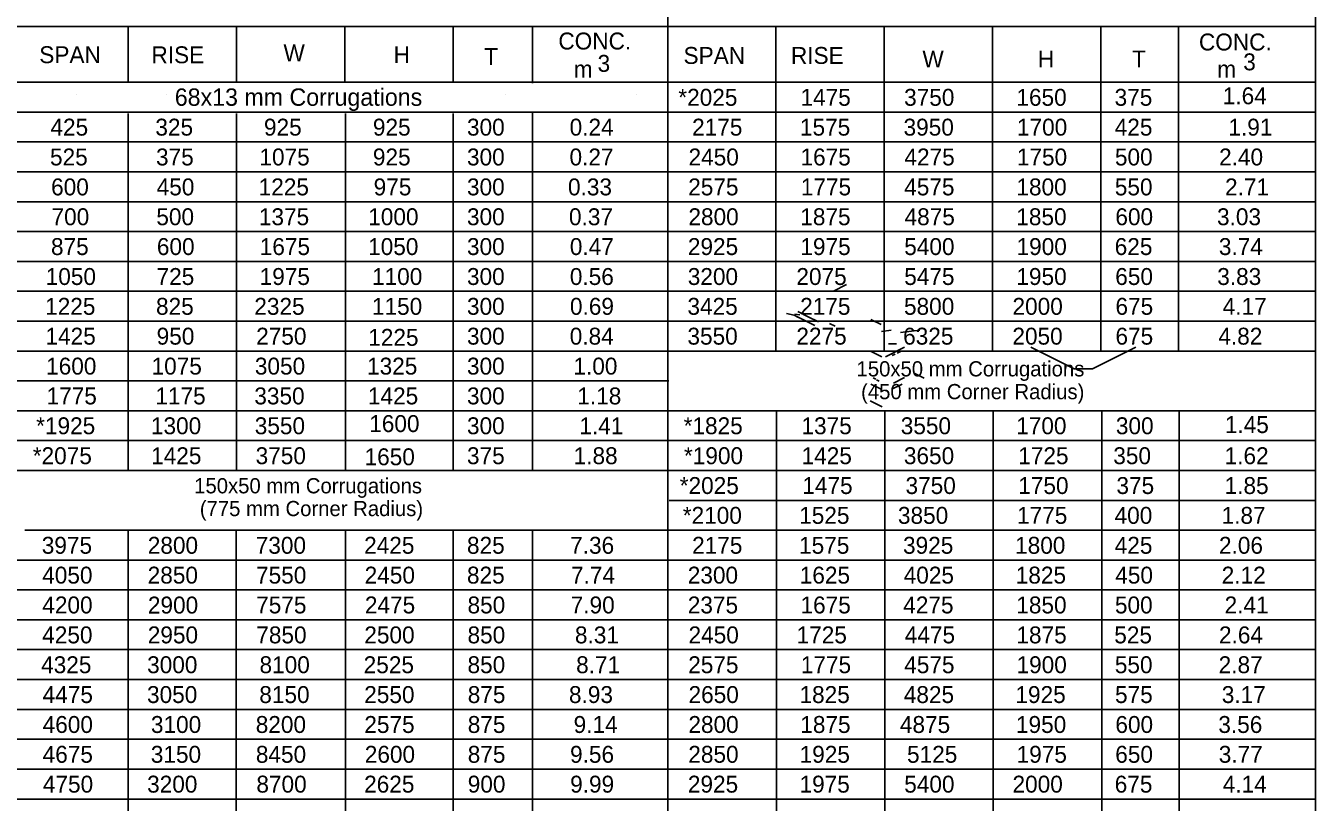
# Model space of a CAD drawing. Extents: x 1083.1 to 1117.1, y 675.4 to 741.4.
# Drawn here: x 1091.76 to 1103.66, y 705.19 to 712.34 of the extents above; entities that cross this region are included whole.
import ezdxf

# ---------------------------------------------------------------- set-up
doc = ezdxf.new("R2010")
doc.units = 0
doc.layers.add('Level 1', color=7, linetype='Continuous')

msp = doc.modelspace()

# ---------------------------------------------------------------- linework, layer by layer
at = {"layer": 'Level 1'}
for p, q in [((1103.658, 698.26), (1103.658, 713.109)), ((1097.684, 699.159), (1097.684, 712.709)), ((1103.658, 712.337), (1086.478, 712.337)), ((1092.703, 711.824), (1092.703, 712.337)), ((1093.703, 711.824), (1093.703, 712.337)), ((1094.702, 711.824), (1094.702, 712.337)), ((1095.702, 711.824), (1095.702, 712.337)), ((1096.433, 711.817), (1096.433, 712.336)), ((1098.68, 709.346), (1098.68, 712.337)), ((1099.68, 709.346), (1099.68, 712.337)), ((1099.68, 711.824), (1099.68, 712.337)), ((1100.679, 709.346), (1100.679, 712.337)), ((1100.679, 711.824), (1100.679, 712.337)), ((1101.679, 709.346), (1101.679, 712.337)), ((1101.679, 711.824), (1101.679, 712.337)), ((1102.395, 709.346), (1102.395, 712.337)), ((1103.658, 711.824), (1086.478, 711.824)), ((1103.658, 711.824), (1086.48, 711.824)), ((1092.227, 711.713), (1092.227, 711.713)), ((1093.055, 711.713), (1093.055, 711.713)), ((1094.051, 711.713), (1094.051, 711.713)), ((1094.176, 711.713), (1094.176, 711.713)), ((1094.197, 711.713), (1094.197, 711.713)), ((1095.055, 711.713), (1095.055, 711.713)), ((1095.181, 711.713), (1095.181, 711.713)), ((1095.202, 711.713), (1095.202, 711.713)), ((1096.186, 711.713), (1096.186, 711.713)), ((1097.394, 711.713), (1097.394, 711.713)), ((1103.658, 711.549), (1086.478, 711.549)), ((1092.703, 708.245), (1092.703, 711.537)), ((1093.703, 708.244), (1093.703, 711.537)), ((1094.708, 708.243), (1094.708, 711.537)), ((1095.702, 708.242), (1095.702, 711.537)), ((1096.433, 708.241), (1096.433, 711.548)), ((1103.658, 711.274), (1086.478, 711.274)), ((1103.658, 710.998), (1086.478, 710.998)), ((1103.658, 710.723), (1086.478, 710.723)), ((1103.658, 710.447), (1086.478, 710.447)), ((1103.658, 710.172), (1086.478, 710.172)), ((1099.213, 709.899), (1099.333, 709.959)), ((1103.658, 709.897), (1086.478, 709.897)), ((1098.85, 709.676), (1098.779, 709.692)), ((1099.04, 709.581), (1098.85, 709.676)), ((1098.89, 709.656), (1098.85, 709.676)), ((1098.901, 709.679), (1098.855, 709.686)), ((1098.977, 709.662), (1098.883, 709.709)), ((1103.658, 709.621), (1086.478, 709.621)), ((1099.072, 709.614), (1098.977, 709.662)), ((1099.228, 709.574), (1099.175, 709.6)), ((1099.65, 709.59), (1099.556, 709.638)), ((1099.655, 709.526), (1099.744, 709.537)), ((1099.83, 709.518), (1100.009, 709.538)), ((1103.658, 709.346), (1086.478, 709.346)), ((1097.681, 709.345), (1103.658, 709.346)), ((1099.658, 709.293), (1099.559, 709.343)), ((1099.692, 709.293), (1099.868, 709.381)), ((1099.792, 709.411), (1099.719, 709.411)), ((1099.754, 709.305), (1099.78, 709.318)), ((1099.799, 709.327), (1099.835, 709.345)), ((1101.032, 709.382), (1101.431, 709.181)), ((1101.602, 709.182), (1102, 709.383)), ((1099.601, 709.086), (1099.576, 709.098)), ((1099.633, 709.069), (1099.609, 709.082)), ((1099.764, 709.049), (1099.867, 709.101)), ((1100.049, 709.095), (1099.955, 709.142)), ((1101.431, 709.181), (1101.602, 709.182)), ((1097.691, 709.071), (1086.478, 709.071)), ((1099.651, 708.994), (1099.557, 709.041)), ((1099.75, 708.994), (1099.844, 709.041)), ((1099.661, 708.832), (1099.551, 708.887)), ((1097.691, 708.795), (1086.478, 708.795)), ((1097.691, 708.795), (1103.665, 708.795)), ((1098.687, 708.214), (1098.687, 708.79)), ((1099.686, 707.555), (1099.686, 708.79)), ((1100.686, 707.623), (1100.686, 708.79)), ((1101.686, 699.159), (1101.686, 708.79)), ((1102.402, 699.159), (1102.402, 708.79)), ((1103.658, 708.52), (1086.478, 708.52)), ((1098.687, 699.159), (1098.687, 708.512)), ((1091.771, 708.245), (1086.478, 708.245)), ((1091.756, 708.246), (1097.684, 708.246)), ((1103.658, 708.245), (1097.687, 708.245)), ((1103.658, 707.969), (1097.694, 707.969)), ((1091.75, 707.694), (1097.684, 707.694)), ((1092.703, 701.086), (1092.703, 707.693)), ((1093.699, 701.085), (1093.699, 707.692)), ((1094.708, 701.085), (1094.708, 707.691)), ((1095.702, 701.086), (1095.702, 707.69)), ((1096.433, 701.087), (1096.433, 707.689)), ((1103.658, 707.694), (1097.684, 707.694)), ((1098.687, 700.427), (1098.687, 707.623)), ((1099.686, 700.427), (1099.686, 707.623)), ((1099.686, 699.159), (1099.686, 707.623)), ((1100.686, 700.427), (1100.686, 707.623)), ((1100.686, 699.159), (1100.686, 707.623)), ((1103.658, 707.419), (1086.478, 707.419)), ((1103.658, 707.144), (1086.478, 707.144)), ((1103.658, 706.868), (1086.478, 706.868)), ((1103.658, 706.593), (1086.478, 706.593)), ((1103.658, 706.317), (1086.478, 706.317)), ((1103.658, 706.317), (1086.48, 706.317)), ((1103.658, 706.042), (1086.478, 706.042)), ((1103.658, 705.767), (1086.478, 705.767)), ((1103.658, 705.491), (1086.478, 705.491)), ((1103.658, 705.216), (1086.478, 705.216))]:
    msp.add_line(p, q, dxfattribs=at)

# ---------------------------------------------------------------- texts
for s, height, p in [('W', 0.156, (1094.137, 712.017)), ('CONC.', 0.156, (1096.673, 712.126)), ('CONC.', 0.156, (1102.583, 712.117)), ('SPAN', 0.156, (1091.884, 712)), ('RISE', 0.156, (1092.919, 711.999)), ('H', 0.156, (1095.153, 712)), ('T', 0.156, (1095.989, 711.984)), ('3', 0.156, (1097.035, 711.92)), ('SPAN', 0.156, (1097.828, 711.993)), ('RISE', 0.156, (1098.819, 711.993)), ('W', 0.156, (1100.032, 711.96)), ('H', 0.156, (1101.097, 711.96)), ('T', 0.156, (1101.966, 711.96)), ('3', 0.156, (1102.992, 711.934)), ('m ', 0.156, (1096.815, 711.867)), ('m ', 0.156, (1102.752, 711.867)), ('68x13 mm Corrugations', 0.16, (1093.134, 711.607)), ('*2025', 0.156, (1097.78, 711.607)), ('1475', 0.156, (1098.907, 711.607)), ('3750', 0.156, (1099.863, 711.607)), ('1650', 0.156, (1100.899, 711.607)), ('375', 0.156, (1101.805, 711.607)), ('1.64', 0.156, (1102.803, 711.621)), ('425', 0.156, (1091.987, 711.332)), ('325', 0.156, (1092.955, 711.332)), ('925', 0.156, (1093.957, 711.332)), ('925', 0.156, (1094.962, 711.332)), ('300', 0.156, (1095.83, 711.332)), ('0.24', 0.156, (1096.777, 711.332)), ('2175', 0.156, (1097.907, 711.332)), ('1575', 0.156, (1098.902, 711.332)), ('3950', 0.156, (1099.858, 711.332)), ('1700', 0.156, (1100.904, 711.332)), ('425', 0.156, (1101.806, 711.332)), ('1.91', 0.156, (1102.855, 711.332)), ('525', 0.156, (1091.983, 711.057)), ('375', 0.156, (1092.961, 711.057)), ('1075', 0.156, (1093.915, 711.057)), ('925', 0.156, (1094.962, 711.057)), ('300', 0.156, (1095.83, 711.057)), ('0.27', 0.156, (1096.776, 711.057)), ('2450', 0.156, (1097.874, 711.057)), ('1675', 0.156, (1098.907, 711.057)), ('4275', 0.156, (1099.866, 711.057)), ('1750', 0.156, (1100.903, 711.057)), ('500', 0.156, (1101.808, 711.057)), ('2.40', 0.156, (1102.769, 711.057)), ('600', 0.156, (1091.993, 710.781)), ('450', 0.156, (1092.967, 710.781)), ('1225', 0.156, (1093.908, 710.781)), ('975', 0.156, (1094.969, 710.781)), ('300', 0.156, (1095.83, 710.781)), ('0.33', 0.156, (1096.762, 710.781)), ('2575', 0.156, (1097.871, 710.781)), ('1775', 0.156, (1098.91, 710.781)), ('4575', 0.156, (1099.864, 710.781)), ('1800', 0.156, (1100.899, 710.781)), ('550', 0.156, (1101.807, 710.781)), ('2.71', 0.156, (1102.824, 710.781)), ('700', 0.156, (1091.997, 710.506)), ('500', 0.156, (1092.964, 710.506)), ('1375', 0.156, (1093.91, 710.506)), ('1000', 0.156, (1094.919, 710.506)), ('300', 0.156, (1095.83, 710.506)), ('0.37', 0.156, (1096.771, 710.506)), ('2800', 0.156, (1097.873, 710.506)), ('1875', 0.156, (1098.905, 710.506)), ('4875', 0.156, (1099.867, 710.506)), ('1850', 0.156, (1100.898, 710.506)), ('600', 0.156, (1101.812, 710.506)), ('3.03', 0.156, (1102.75, 710.506)), ('875', 0.156, (1091.992, 710.231)), ('600', 0.156, (1092.969, 710.231)), ('1675', 0.156, (1093.918, 710.231)), ('1050', 0.156, (1094.918, 710.231)), ('300', 0.156, (1095.83, 710.231)), ('0.47', 0.156, (1096.779, 710.231)), ('2925', 0.156, (1097.868, 710.231)), ('1975', 0.156, (1098.906, 710.231)), ('5400', 0.156, (1099.864, 710.231)), ('1900', 0.156, (1100.9, 710.231)), ('625', 0.156, (1101.806, 710.231)), ('3.74', 0.156, (1102.767, 710.231)), ('1050', 0.156, (1091.943, 709.955)), ('725', 0.156, (1092.966, 709.955)), ('1975', 0.156, (1093.917, 709.955)), ('1100', 0.156, (1094.954, 709.955)), ('300', 0.156, (1095.83, 709.955)), ('0.56', 0.156, (1096.779, 709.955)), ('3200', 0.156, (1097.867, 709.955)), ('2075', 0.156, (1098.869, 709.955)), ('5475', 0.156, (1099.864, 709.955)), ('1950', 0.156, (1100.899, 709.955)), ('650', 0.156, (1101.811, 709.955)), ('3.83', 0.156, (1102.752, 709.955)), ('1225', 0.156, (1091.938, 709.68)), ('825', 0.156, (1092.961, 709.68)), ('2325', 0.156, (1093.868, 709.68)), ('1150', 0.156, (1094.953, 709.68)), ('300', 0.156, (1095.83, 709.68)), ('0.69', 0.156, (1096.78, 709.68)), ('3425', 0.156, (1097.864, 709.68)), ('2175', 0.156, (1098.904, 709.68)), ('5800', 0.156, (1099.862, 709.68)), ('2000', 0.156, (1100.863, 709.68)), ('675', 0.156, (1101.813, 709.68)), ('4.17', 0.156, (1102.802, 709.68)), ('1425', 0.156, (1091.941, 709.405)), ('950', 0.156, (1092.967, 709.405)), ('2750', 0.156, (1093.885, 709.405)), ('1225', 0.156, (1094.919, 709.394)), ('300', 0.156, (1095.83, 709.405)), ('0.84', 0.156, (1096.778, 709.405)), ('3550', 0.156, (1097.864, 709.405)), ('2275', 0.156, (1098.869, 709.405)), ('6325', 0.156, (1099.854, 709.405)), ('2050', 0.156, (1100.862, 709.405)), ('675', 0.156, (1101.813, 709.405)), ('4.82', 0.156, (1102.762, 709.405)), ('1600', 0.156, (1091.947, 709.129)), ('1075', 0.156, (1092.92, 709.129)), ('3050', 0.156, (1093.873, 709.129)), ('1325', 0.156, (1094.908, 709.129)), ('300', 0.156, (1095.83, 709.129)), ('1.00', 0.156, (1096.812, 709.129)), ('150x50 mm Corrugations', 0.14, (1099.424, 709.112)), ('1775', 0.156, (1091.951, 708.854)), ('1175', 0.156, (1092.955, 708.854)), ('3350', 0.156, (1093.868, 708.854)), ('1425', 0.156, (1094.916, 708.854)), ('300', 0.156, (1095.83, 708.854)), ('1.18', 0.156, (1096.848, 708.854)), ('(450 mm Corner Radius)', 0.14, (1099.466, 708.902)), ('*1925', 0.156, (1091.855, 708.579)), ('1300', 0.156, (1092.914, 708.579)), ('3550', 0.156, (1093.872, 708.579)), ('1600', 0.156, (1094.928, 708.599)), ('300', 0.156, (1095.83, 708.579)), ('1.41', 0.156, (1096.867, 708.579)), ('*1825', 0.156, (1097.829, 708.579)), ('1375', 0.156, (1098.916, 708.579)), ('3550', 0.156, (1099.832, 708.579)), ('1700', 0.156, (1100.897, 708.579)), ('300', 0.156, (1101.817, 708.579)), ('1.45', 0.156, (1102.822, 708.59)), ('*2075', 0.156, (1091.824, 708.303)), ('1425', 0.156, (1092.916, 708.303)), ('3750', 0.156, (1093.88, 708.303)), ('1650', 0.156, (1094.885, 708.293)), ('375', 0.156, (1095.83, 708.303)), ('1.88', 0.156, (1096.814, 708.303)), ('*1900', 0.156, (1097.832, 708.303)), ('1425', 0.156, (1098.917, 708.303)), ('3650', 0.156, (1099.861, 708.303)), ('1725', 0.156, (1100.916, 708.303)), ('350', 0.156, (1101.793, 708.303)), ('1.62', 0.156, (1102.82, 708.303)), ('150x50 mm Corrugations', 0.14, (1093.313, 708.034)), ('*2025', 0.156, (1097.793, 708.028)), ('1475', 0.156, (1098.924, 708.028)), ('3750', 0.156, (1099.876, 708.028)), ('1750', 0.156, (1100.916, 708.028)), ('375', 0.156, (1101.822, 708.028)), ('1.85', 0.156, (1102.82, 708.028)), ('(775 mm Corner Radius)', 0.14, (1093.365, 707.824)), ('*2100', 0.156, (1097.821, 707.753)), ('1525', 0.156, (1098.895, 707.753)), ('3850', 0.156, (1099.806, 707.753)), ('1775', 0.156, (1100.905, 707.753)), ('400', 0.156, (1101.805, 707.753)), ('1.87', 0.156, (1102.792, 707.753)), ('3975', 0.156, (1091.907, 707.477)), ('2800', 0.156, (1092.885, 707.477)), ('7300', 0.156, (1093.881, 707.477)), ('2425', 0.156, (1094.881, 707.477)), ('825', 0.156, (1095.83, 707.477)), ('7.36', 0.156, (1096.782, 707.477)), ('2175', 0.156, (1097.907, 707.477)), ('1575', 0.156, (1098.894, 707.477)), ('3925', 0.156, (1099.853, 707.477)), ('1800', 0.156, (1100.887, 707.477)), ('425', 0.156, (1101.806, 707.477)), ('2.06', 0.156, (1102.768, 707.477)), ('4050', 0.156, (1091.911, 707.202)), ('2850', 0.156, (1092.884, 707.202)), ('7550', 0.156, (1093.884, 707.202)), ('2450', 0.156, (1094.886, 707.202)), ('825', 0.156, (1095.83, 707.202)), ('7.74', 0.156, (1096.79, 707.202)), ('2300', 0.156, (1097.867, 707.202)), ('1625', 0.156, (1098.9, 707.202)), ('4025', 0.156, (1099.859, 707.202)), ('1825', 0.156, (1100.893, 707.202)), ('450', 0.156, (1101.811, 707.202)), ('2.12', 0.156, (1102.793, 707.202)), ('4200', 0.156, (1091.912, 706.927)), ('2900', 0.156, (1092.886, 706.926)), ('7575', 0.156, (1093.885, 706.927)), ('2475', 0.156, (1094.888, 706.927)), ('850', 0.156, (1095.835, 706.927)), ('7.90', 0.156, (1096.787, 706.927)), ('2375', 0.156, (1097.867, 706.927)), ('1675', 0.156, (1098.907, 706.927)), ('4275', 0.156, (1099.855, 706.927)), ('1850', 0.156, (1100.898, 706.927)), ('500', 0.156, (1101.808, 706.927)), ('2.41', 0.156, (1102.82, 706.927)), ('4250', 0.156, (1091.911, 706.651)), ('2950', 0.156, (1092.885, 706.651)), ('7850', 0.156, (1093.886, 706.651)), ('2500', 0.156, (1094.883, 706.651)), ('850', 0.156, (1095.835, 706.651)), ('8.31', 0.156, (1096.826, 706.651)), ('2450', 0.156, (1097.874, 706.651)), ('1725', 0.156, (1098.871, 706.651)), ('4475', 0.156, (1099.869, 706.651)), ('1875', 0.156, (1100.899, 706.651)), ('525', 0.156, (1101.802, 706.651)), ('2.64', 0.156, (1102.768, 706.651)), ('4325', 0.156, (1091.901, 706.376)), ('3000', 0.156, (1092.879, 706.376)), ('8100', 0.156, (1093.916, 706.376)), ('2525', 0.156, (1094.877, 706.376)), ('850', 0.156, (1095.835, 706.376)), ('8.71', 0.156, (1096.837, 706.376)), ('2575', 0.156, (1097.871, 706.376)), ('1775', 0.156, (1098.91, 706.376)), ('4575', 0.156, (1099.864, 706.376)), ('1900', 0.156, (1100.9, 706.376)), ('550', 0.156, (1101.807, 706.376)), ('2.87', 0.156, (1102.765, 706.376)), ('4475', 0.156, (1091.915, 706.101)), ('3050', 0.156, (1092.878, 706.101)), ('8150', 0.156, (1093.914, 706.101)), ('2550', 0.156, (1094.882, 706.101)), ('875', 0.156, (1095.837, 706.101)), ('8.93', 0.156, (1096.771, 706.101)), ('2650', 0.156, (1097.874, 706.101)), ('1825', 0.156, (1098.898, 706.101)), ('4825', 0.156, (1099.86, 706.101)), ('1925', 0.156, (1100.89, 706.101)), ('575', 0.156, (1101.809, 706.101)), ('3.17', 0.156, (1102.794, 706.101)), ('4600', 0.156, (1091.915, 705.825)), ('3100', 0.156, (1092.914, 705.825)), ('8200', 0.156, (1093.881, 705.825)), ('2575', 0.156, (1094.883, 705.825)), ('875', 0.156, (1095.837, 705.825)), ('9.14', 0.156, (1096.814, 705.825)), ('2800', 0.156, (1097.873, 705.825)), ('1875', 0.156, (1098.905, 705.825)), ('4875', 0.156, (1099.824, 705.825)), ('1950', 0.156, (1100.895, 705.825)), ('600', 0.156, (1101.812, 705.825)), ('3.56', 0.156, (1102.762, 705.825)), ('4675', 0.156, (1091.915, 705.55)), ('3150', 0.156, (1092.913, 705.55)), ('8450', 0.156, (1093.882, 705.55)), ('2600', 0.156, (1094.887, 705.55)), ('875', 0.156, (1095.837, 705.55)), ('9.56', 0.156, (1096.781, 705.55)), ('2850', 0.156, (1097.872, 705.55)), ('1925', 0.156, (1098.899, 705.55)), ('5125', 0.156, (1099.89, 705.55)), ('1975', 0.156, (1100.901, 705.55)), ('650', 0.156, (1101.811, 705.55)), ('3.77', 0.156, (1102.766, 705.55)), ('4750', 0.156, (1091.917, 705.275)), ('3200', 0.156, (1092.879, 705.275)), ('8700', 0.156, (1093.887, 705.275)), ('2625', 0.156, (1094.881, 705.275)), ('900', 0.156, (1095.837, 705.275)), ('9.99', 0.156, (1096.782, 705.275)), ('2925', 0.156, (1097.868, 705.275)), ('1975', 0.156, (1098.898, 705.275)), ('5400', 0.156, (1099.864, 705.275)), ('2000', 0.156, (1100.863, 705.275)), ('675', 0.156, (1101.806, 705.275)), ('4.14', 0.156, (1102.803, 705.275))]:
    msp.add_text(s, height=height, dxfattribs=at).set_placement(p)

doc.saveas('drawing.dxf')
